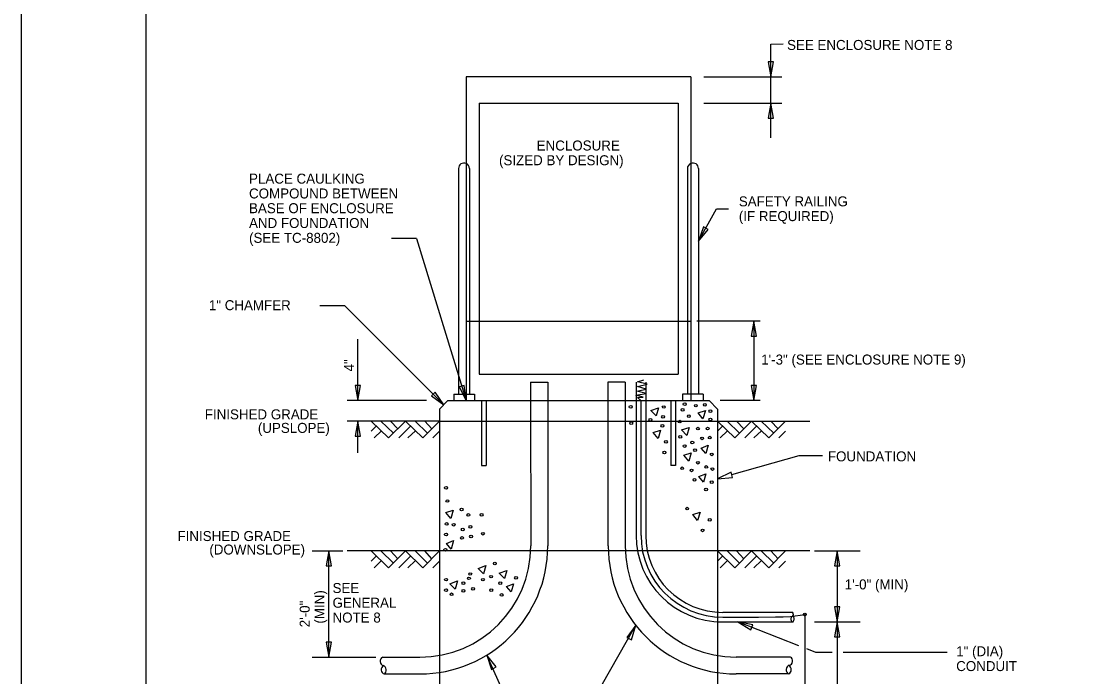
# Model space of a CAD drawing. Extents: x 1299104.8 to 1299141.6, y 239639.8 to 239661.8.
# Drawn here: x 1299104.8 to 1299117.69, y 239644.86 to 239652.72 of the extents above; entities that cross this region are included whole.
import ezdxf

# ---------------------------------------------------------------- set-up
doc = ezdxf.new("R2010")
doc.units = 0
for name, color, linetype in [('GS_plotshape_p', 7, 'Continuous'), ('Level 1', 7, 'Continuous'), ('PTEXT', 7, 'Continuous')]:
    doc.layers.add(name, color=color, linetype=linetype)

msp = doc.modelspace()

# ---------------------------------------------------------------- linework, layer by layer
at = {"layer": 'GS_plotshape_p'}
msp.add_lwpolyline([(1299104.802, 239661.791), (1299138.802, 239661.791), (1299138.802, 239639.791), (1299104.802, 239639.791)], close=True, dxfattribs=at)
at = {"layer": 'Level 1'}
msp.add_lwpolyline([(1299138.302, 239640.291), (1299106.302, 239640.291), (1299106.302, 239661.291), (1299138.302, 239661.291)], close=True, dxfattribs=at)
at = {"layer": 'PTEXT'}
for p, q in [((1299113.778, 239652.24), (1299113.81, 239652.06)), ((1299113.842, 239652.24), (1299113.778, 239652.24)), ((1299113.81, 239652.06), (1299113.842, 239652.24)), ((1299110.147, 239652.06), (1299110.147, 239648.171)), ((1299112.851, 239652.06), (1299110.147, 239652.06)), ((1299112.851, 239652.06), (1299112.851, 239648.171)), ((1299113.007, 239652.06), (1299113.943, 239652.06)), ((1299110.303, 239651.742), (1299112.695, 239651.742)), ((1299110.303, 239651.742), (1299110.303, 239648.489)), ((1299112.695, 239651.742), (1299112.695, 239648.489)), ((1299113.007, 239651.742), (1299113.943, 239651.742)), ((1299113.81, 239651.742), (1299113.778, 239651.562)), ((1299113.81, 239651.326), (1299113.81, 239651.742)), ((1299113.842, 239651.562), (1299113.81, 239651.742)), ((1299113.778, 239651.562), (1299113.842, 239651.562)), ((1299110.057, 239650.958), (1299110.057, 239648.247)), ((1299110.189, 239650.958), (1299110.189, 239648.247)), ((1299112.808, 239650.958), (1299112.808, 239648.247)), ((1299112.941, 239650.958), (1299112.941, 239648.247)), ((1299113.001, 239650.258), (1299112.941, 239650.086)), ((1299113.057, 239650.227), (1299113.001, 239650.258)), ((1299109.551, 239650.118), (1299109.251, 239650.118)), ((1299109.551, 239650.118), (1299110.147, 239648.171)), ((1299112.941, 239650.086), (1299113.057, 239650.227)), ((1299108.691, 239649.31), (1299108.39, 239649.31)), ((1299109.88, 239648.121), (1299108.691, 239649.31)), ((1299110.147, 239649.124), (1299112.851, 239649.124)), ((1299113.683, 239649.124), (1299112.92, 239649.124)), ((1299113.608, 239649.124), (1299113.576, 239648.944)), ((1299113.608, 239649.124), (1299113.608, 239648.171)), ((1299113.639, 239648.944), (1299113.608, 239649.124)), ((1299113.576, 239648.944), (1299113.639, 239648.944)), ((1299108.846, 239648.171), (1299108.846, 239648.906)), ((1299110.303, 239648.489), (1299112.695, 239648.489)), ((1299108.814, 239648.351), (1299108.846, 239648.171)), ((1299108.878, 239648.351), (1299108.814, 239648.351)), ((1299108.846, 239648.171), (1299108.878, 239648.351)), ((1299110.124, 239648.352), (1299110.064, 239648.334)), ((1299110.064, 239648.334), (1299110.147, 239648.171)), ((1299110.147, 239648.171), (1299110.124, 239648.352)), ((1299110.921, 239648.391), (1299111.129, 239648.391)), ((1299110.921, 239648.391), (1299110.921, 239648.171)), ((1299111.129, 239648.391), (1299111.129, 239648.171)), ((1299112.059, 239648.391), (1299111.851, 239648.391)), ((1299111.851, 239648.391), (1299111.851, 239648.171)), ((1299112.059, 239648.391), (1299112.059, 239648.171)), ((1299112.192, 239648.391), (1299112.192, 239646.551)), ((1299112.307, 239648.391), (1299112.307, 239646.551)), ((1299113.576, 239648.351), (1299113.608, 239648.171)), ((1299113.639, 239648.351), (1299113.576, 239648.351)), ((1299113.608, 239648.171), (1299113.639, 239648.351)), ((1299109.672, 239648.171), (1299108.719, 239648.171)), ((1299109.775, 239648.27), (1299109.73, 239648.226)), ((1299109.73, 239648.226), (1299109.88, 239648.121)), ((1299109.88, 239648.121), (1299109.775, 239648.27)), ((1299109.829, 239648.067), (1299109.927, 239648.171)), ((1299109.927, 239648.171), (1299113.07, 239648.171)), ((1299109.999, 239648.247), (1299110.147, 239648.247)), ((1299109.999, 239648.247), (1299109.999, 239648.171)), ((1299110.147, 239648.247), (1299110.247, 239648.247)), ((1299110.247, 239648.247), (1299110.247, 239648.171)), ((1299110.332, 239648.171), (1299110.332, 239647.391)), ((1299110.389, 239648.171), (1299110.389, 239647.391)), ((1299110.921, 239648.171), (1299110.926, 239646.424)), ((1299111.129, 239648.171), (1299111.129, 239646.424)), ((1299111.851, 239648.171), (1299111.851, 239646.424)), ((1299112.059, 239648.171), (1299112.059, 239646.424)), ((1299112.249, 239648.171), (1299112.249, 239646.551)), ((1299112.608, 239648.171), (1299112.608, 239647.391)), ((1299112.666, 239648.171), (1299112.666, 239647.391)), ((1299112.75, 239648.247), (1299112.75, 239648.171)), ((1299112.851, 239648.247), (1299112.75, 239648.247)), ((1299112.999, 239648.247), (1299112.851, 239648.247)), ((1299112.999, 239648.247), (1299112.999, 239648.171)), ((1299113.07, 239648.171), (1299113.169, 239648.067)), ((1299113.683, 239648.171), (1299113.203, 239648.171)), ((1299109.829, 239648.067), (1299109.829, 239643.03)), ((1299113.169, 239648.067), (1299113.169, 239643.03)), ((1299109.829, 239647.924), (1299108.719, 239647.924)), ((1299108.846, 239647.924), (1299108.814, 239647.744)), ((1299108.846, 239647.543), (1299108.846, 239647.924)), ((1299108.878, 239647.744), (1299108.846, 239647.924)), ((1299109.216, 239647.721), (1299109.008, 239647.924)), ((1299109.274, 239647.779), (1299109.124, 239647.924)), ((1299109.419, 239647.924), (1299109.216, 239647.721)), ((1299109.326, 239647.831), (1299109.239, 239647.924)), ((1299109.627, 239647.721), (1299109.419, 239647.924)), ((1299109.684, 239647.779), (1299109.534, 239647.924)), ((1299109.829, 239647.924), (1299109.627, 239647.721)), ((1299109.736, 239647.831), (1299109.65, 239647.924)), ((1299109.829, 239647.924), (1299114.278, 239647.924)), ((1299113.377, 239647.721), (1299113.169, 239647.924)), ((1299113.434, 239647.779), (1299113.284, 239647.924)), ((1299113.579, 239647.924), (1299113.377, 239647.721)), ((1299113.486, 239647.831), (1299113.4, 239647.924)), ((1299113.787, 239647.721), (1299113.579, 239647.924)), ((1299113.845, 239647.779), (1299113.694, 239647.924)), ((1299113.989, 239647.924), (1299113.787, 239647.721)), ((1299113.897, 239647.831), (1299113.81, 239647.924)), ((1299109.072, 239647.866), (1299109.008, 239647.802)), ((1299109.13, 239647.808), (1299109.043, 239647.721)), ((1299109.482, 239647.866), (1299109.338, 239647.721)), ((1299109.54, 239647.808), (1299109.447, 239647.721)), ((1299109.829, 239647.802), (1299109.748, 239647.721)), ((1299113.232, 239647.866), (1299113.169, 239647.802)), ((1299113.29, 239647.808), (1299113.203, 239647.721)), ((1299113.642, 239647.866), (1299113.498, 239647.721)), ((1299113.7, 239647.808), (1299113.608, 239647.721)), ((1299113.989, 239647.802), (1299113.908, 239647.721)), ((1299108.814, 239647.744), (1299108.878, 239647.744)), ((1299110.332, 239647.391), (1299110.389, 239647.391)), ((1299112.666, 239647.391), (1299112.608, 239647.391)), ((1299113.333, 239647.309), (1299113.168, 239647.229)), ((1299113.35, 239647.248), (1299113.333, 239647.309)), ((1299113.168, 239647.229), (1299113.35, 239647.248)), ((1299108.297, 239646.364), (1299108.667, 239646.364)), ((1299108.497, 239646.364), (1299108.465, 239646.184)), ((1299108.497, 239645.089), (1299108.497, 239646.364)), ((1299108.529, 239646.184), (1299108.497, 239646.364)), ((1299109.829, 239646.364), (1299108.719, 239646.364)), ((1299109.216, 239646.161), (1299109.008, 239646.364)), ((1299109.072, 239646.306), (1299109.008, 239646.242)), ((1299109.13, 239646.248), (1299109.043, 239646.161)), ((1299109.274, 239646.219), (1299109.124, 239646.364)), ((1299109.419, 239646.364), (1299109.216, 239646.161)), ((1299109.326, 239646.271), (1299109.239, 239646.364)), ((1299109.482, 239646.306), (1299109.338, 239646.161)), ((1299109.627, 239646.161), (1299109.419, 239646.364)), ((1299109.54, 239646.248), (1299109.447, 239646.161)), ((1299109.684, 239646.219), (1299109.534, 239646.364)), ((1299109.829, 239646.364), (1299109.627, 239646.161)), ((1299109.736, 239646.271), (1299109.65, 239646.364)), ((1299109.829, 239646.242), (1299109.748, 239646.161)), ((1299113.169, 239646.364), (1299109.829, 239646.364)), ((1299114.278, 239646.364), (1299113.169, 239646.364)), ((1299113.377, 239646.161), (1299113.169, 239646.364)), ((1299113.232, 239646.306), (1299113.169, 239646.242)), ((1299113.29, 239646.248), (1299113.203, 239646.161)), ((1299113.434, 239646.219), (1299113.284, 239646.364)), ((1299113.579, 239646.364), (1299113.377, 239646.161)), ((1299113.486, 239646.271), (1299113.4, 239646.364)), ((1299113.642, 239646.306), (1299113.498, 239646.161)), ((1299113.787, 239646.161), (1299113.579, 239646.364)), ((1299113.7, 239646.248), (1299113.608, 239646.161)), ((1299113.845, 239646.219), (1299113.694, 239646.364)), ((1299113.989, 239646.364), (1299113.787, 239646.161)), ((1299113.897, 239646.271), (1299113.81, 239646.364)), ((1299113.989, 239646.242), (1299113.908, 239646.161)), ((1299114.335, 239646.364), (1299114.885, 239646.364)), ((1299114.61, 239646.364), (1299114.578, 239646.184)), ((1299114.61, 239646.364), (1299114.61, 239645.511)), ((1299114.641, 239646.184), (1299114.61, 239646.364)), ((1299108.465, 239646.184), (1299108.529, 239646.184)), ((1299114.578, 239646.184), (1299114.641, 239646.184)), ((1299113.232, 239645.627), (1299114.07, 239645.627)), ((1299114.219, 239645.599), (1299114.219, 239643.649)), ((1299114.578, 239645.691), (1299114.61, 239645.511)), ((1299114.641, 239645.691), (1299114.578, 239645.691)), ((1299114.61, 239645.511), (1299114.641, 239645.691)), ((1299111.092, 239643.553), (1299112.187, 239645.471)), ((1299112.187, 239645.471), (1299112.078, 239645.324)), ((1299112.135, 239645.296), (1299112.187, 239645.471)), ((1299113.169, 239645.511), (1299114.07, 239645.511)), ((1299113.232, 239645.569), (1299113.661, 239645.569)), ((1299113.232, 239645.511), (1299113.556, 239645.511)), ((1299113.595, 239645.475), (1299113.416, 239645.511)), ((1299113.416, 239645.511), (1299113.572, 239645.416)), ((1299113.572, 239645.416), (1299113.595, 239645.475)), ((1299114.335, 239645.511), (1299114.885, 239645.511)), ((1299114.61, 239645.511), (1299114.578, 239645.331)), ((1299114.641, 239645.331), (1299114.61, 239645.511)), ((1299114.61, 239645.511), (1299114.61, 239643.161)), ((1299108.465, 239645.269), (1299108.497, 239645.089)), ((1299108.529, 239645.269), (1299108.465, 239645.269)), ((1299108.497, 239645.089), (1299108.529, 239645.269)), ((1299112.078, 239645.324), (1299112.135, 239645.296)), ((1299114.578, 239645.331), (1299114.641, 239645.331)), ((1299108.297, 239645.089), (1299109.063, 239645.089)), ((1299109.145, 239645.089), (1299109.439, 239645.089)), ((1299109.439, 239645.089), (1299109.591, 239645.089)), ((1299110.51, 239644.97), (1299110.397, 239645.114)), ((1299110.397, 239645.114), (1299110.453, 239644.94)), ((1299114.045, 239645.089), (1299113.394, 239645.089)), ((1299110.453, 239644.94), (1299110.51, 239644.97)), ((1299109.164, 239644.886), (1299109.457, 239644.886)), ((1299109.457, 239644.886), (1299109.591, 239644.886)), ((1299114.025, 239644.886), (1299113.394, 239644.886))]:
    msp.add_line(p, q, dxfattribs=at)
for points in [[(1299113.81, 239652.06), (1299113.81, 239652.453), (1299113.96, 239652.455)], [(1299113.81, 239651.742), (1299113.81, 239652.06)], [(1299112.941, 239650.086), (1299113.158, 239650.475), (1299113.301, 239650.475)], [(1299112.249, 239648.171), (1299112.208, 239648.208), (1299112.275, 239648.213), (1299112.189, 239648.237), (1299112.314, 239648.256), (1299112.199, 239648.285), (1299112.314, 239648.309), (1299112.208, 239648.338), (1299112.323, 239648.367), (1299112.208, 239648.396), (1299112.285, 239648.42)], [(1299112.37, 239648.05), (1299112.462, 239648.084), (1299112.434, 239647.986), (1299112.37, 239648.05)], [(1299112.937, 239648.021), (1299113.024, 239648.05), (1299112.995, 239647.951), (1299112.937, 239648.021)], [(1299112.397, 239647.785), (1299112.484, 239647.814), (1299112.455, 239647.716), (1299112.397, 239647.785)], [(1299112.735, 239647.819), (1299112.828, 239647.847), (1299112.799, 239647.749), (1299112.735, 239647.819)], [(1299112.766, 239647.513), (1299112.853, 239647.542), (1299112.824, 239647.444), (1299112.766, 239647.513)], [(1299112.972, 239647.599), (1299113.059, 239647.634), (1299113.03, 239647.535), (1299112.972, 239647.599)], [(1299114.431, 239647.505), (1299114.146, 239647.505), (1299113.339, 239647.279)], [(1299112.944, 239647.26), (1299113.031, 239647.289), (1299113.002, 239647.19), (1299112.944, 239647.26)], [(1299109.904, 239646.825), (1299109.991, 239646.854), (1299109.962, 239646.755), (1299109.904, 239646.825)], [(1299112.873, 239646.8), (1299112.96, 239646.829), (1299112.931, 239646.73), (1299112.873, 239646.8)], [(1299109.91, 239646.455), (1299109.996, 239646.49), (1299109.968, 239646.386), (1299109.91, 239646.455)], [(1299110.291, 239646.154), (1299110.384, 239646.189), (1299110.355, 239646.091), (1299110.291, 239646.154)], [(1299110.545, 239646.097), (1299110.638, 239646.131), (1299110.609, 239646.033), (1299110.545, 239646.097)], [(1299109.95, 239645.97), (1299110.043, 239646.004), (1299110.014, 239645.906), (1299109.95, 239645.97)], [(1299110.632, 239645.935), (1299110.719, 239645.97), (1299110.69, 239645.871), (1299110.632, 239645.935)], [(1299113.661, 239645.569), (1299113.868, 239645.572), (1299113.959, 239645.574), (1299114.048, 239645.576), (1299114.219, 239645.599)], [(1299114.147, 239645.225), (1299113.416, 239645.511)], [(1299111.222, 239643.553), (1299111.092, 239643.553), (1299110.397, 239645.114)], [(1299114.55, 239645.145), (1299114.353, 239645.145), (1299114.245, 239645.187)], [(1299115.929, 239645.145), (1299114.681, 239645.145)]]:
    msp.add_lwpolyline(points, dxfattribs=at)
msp.add_circle((1299114.219, 239645.599), 0.0173, dxfattribs=at)
for centre, radius, start, end in [((1299110.123, 239650.958), 0.0661, 69.0442, 180), ((1299110.123, 239650.958), 0.0661, 0, 69.0464), ((1299112.874, 239650.958), 0.0661, 110.9536, 180), ((1299112.874, 239650.958), 0.0661, 0, 110.9558), ((1299113.232, 239646.551), 1.04, 180, 270), ((1299113.232, 239646.551), 0.982, 180, 270), ((1299113.232, 239646.551), 0.925, 180, 270), ((1299109.591, 239646.424), 1.335, 270, 360), ((1299109.591, 239646.424), 1.538, 270, 360), ((1299113.394, 239646.424), 1.538, 180, 270), ((1299113.394, 239646.424), 1.538, 180, 270), ((1299113.394, 239646.424), 1.335, 180, 270), ((1299113.394, 239646.424), 1.335, 180, 270)]:
    msp.add_arc(centre, radius, start, end, dxfattribs=at)
for centre in [(1299112.126, 239648.094), (1299112.524, 239648.093), (1299112.75, 239648.059), (1299112.775, 239648.126), (1299112.909, 239648.109), (1299113.017, 239648.118), (1299113.084, 239648.043), (1299112.133, 239647.9), (1299112.363, 239647.938), (1299112.515, 239647.976), (1299112.716, 239647.917), (1299112.825, 239647.984), (1299113.084, 239647.942), (1299112.507, 239647.867), (1299112.934, 239647.833), (1299113.051, 239647.833), (1299112.549, 239647.675), (1299112.722, 239647.734), (1299112.867, 239647.666), (1299112.984, 239647.716), (1299113.076, 239647.725), (1299112.532, 239647.546), (1299112.775, 239647.624), (1299112.9, 239647.574), (1299113.101, 239647.524), (1299112.934, 239647.424), (1299112.745, 239647.357), (1299112.858, 239647.332), (1299113.034, 239647.373), (1299113.109, 239647.348), (1299112.893, 239647.219), (1299113.101, 239647.189), (1299109.906, 239647.123), (1299113.033, 239647.102), (1299109.923, 239646.964), (1299112.805, 239646.872), (1299110.093, 239646.862), (1299110.174, 239646.796), (1299110.333, 239646.797), (1299113.076, 239646.738), (1299109.914, 239646.688), (1299109.998, 239646.679), (1299110.107, 239646.621), (1299110.199, 239646.654), (1299112.99, 239646.611), (1299109.906, 239646.562), (1299110.098, 239646.52), (1299110.207, 239646.537), (1299110.349, 239646.571), (1299109.898, 239646.378), (1299110.493, 239646.213), (1299109.906, 239646.019), (1299110.115, 239645.977), (1299110.182, 239646.035), (1299110.197, 239646.087), (1299110.349, 239646.019), (1299110.448, 239646.055), (1299110.558, 239645.977), (1299110.748, 239646.041), (1299109.906, 239645.893), (1299109.973, 239645.843), (1299110.115, 239645.885), (1299110.232, 239645.91), (1299110.45, 239645.893), (1299110.575, 239645.835)]:
    msp.add_ellipse(centre, major_axis=(-0.0177, 0), ratio=0.9, dxfattribs=at)
for centre, major_axis, ratio, start_param, end_param in [((1299114.061, 239645.602), (0, 0.0272), 0.806011, 3.296806, 5.871301), ((1299114.073, 239645.544), (0, -0.0332), 0.660349, 3.526651, 6.169081), ((1299114.068, 239645.547), (0, 0.0364), 0.601771, 3.255697, 5.918239), ((1299109.157, 239645.039), (0, -0.0522), 0.840684, 3.402073, 6.169081), ((1299114.028, 239645.042), (0, 0.0522), 0.840684, 3.255697, 5.871301), ((1299109.173, 239644.939), (0, -0.054), 0.840684, 3.617308, 6.07181), ((1299109.143, 239644.934), (0, 0.054), 0.840684, 3.616353, 6.096118), ((1299114.041, 239644.937), (0, -0.054), 0.840684, 3.32866, 5.92796), ((1299114.01, 239644.937), (0, 0.054), 0.840684, 3.496818, 5.926596)]:
    msp.add_ellipse(centre, major_axis=major_axis, ratio=ratio, start_param=start_param, end_param=end_param, dxfattribs=at)

# ---------------------------------------------------------------- texts
for s, p in [('SEE ENCLOSURE NOTE 8', (1299114.006, 239652.382)), ('ENCLOSURE', (1299110.996, 239651.174)), ('(SIZED BY DESIGN)', (1299110.543, 239650.997)), ('PLACE CAULKING', (1299107.538, 239650.776)), ('COMPOUND BETWEEN', (1299107.538, 239650.598)), ('SAFETY RAILING', (1299113.426, 239650.503)), ('BASE OF ENCLOSURE', (1299107.538, 239650.421)), ('AND FOUNDATION', (1299107.538, 239650.243)), ('(IF REQUIRED)', (1299113.426, 239650.326)), ('(SEE TC-8802)', (1299107.538, 239650.065)), ('1" CHAMFER', (1299107.055, 239649.256)), ('1\'-3" (SEE ENCLOSURE NOTE 9)', (1299113.695, 239648.603)), ('FINISHED GRADE', (1299107.006, 239647.945)), ('(UPSLOPE)', (1299107.644, 239647.782)), ('FOUNDATION', (1299114.497, 239647.44)), ('FINISHED GRADE', (1299106.678, 239646.483)), ('(DOWNSLOPE)', (1299107.061, 239646.321)), ('SEE', (1299108.542, 239645.859)), ('GENERAL', (1299108.542, 239645.682)), ('NOTE 8', (1299108.542, 239645.504)), ('1" (DIA)', (1299116.039, 239645.099)), ('CONDUIT', (1299116.039, 239644.921))]:
    msp.add_text(s, height=0.12, dxfattribs=at).set_placement(p)
for s, rotation, p in [('4" ', 90, (1299108.801, 239648.52)), ('1\'-0" (MIN)', 360, (1299114.699, 239645.902)), ('(MIN)', 90, (1299108.445, 239645.491)), ('2\'-0"', 90, (1299108.267, 239645.447))]:
    msp.add_text(s, height=0.12, rotation=rotation, dxfattribs=at).set_placement(p)

doc.saveas('drawing.dxf')
